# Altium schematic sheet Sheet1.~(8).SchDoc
size A4
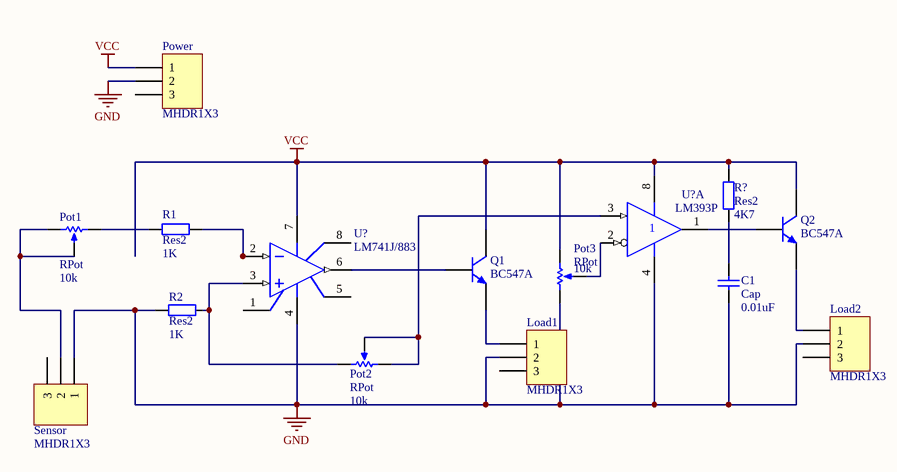
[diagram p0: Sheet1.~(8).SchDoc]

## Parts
(Parts that share a designator on the sheet are numbered #1, #2 ... from top to bottom, then left to right.)
C1  Cap  value 0.01uF  [RAD-0.3]
Load1  MHDR1X3  [MHDR1X3]
Load2  MHDR1X3  [MHDR1X3]
Pot1  RPot  value 10k  [VR5]
Pot2  RPot  value 10k  [VR5]
Pot3  RPot  value 10k  [VR5]
Power  MHDR1X3  [MHDR1X3]
Q1  BC547A  [SOT54]
Q2  BC547A  [SOT54]
R1  Res2  value 1K  [AXIAL-0.4]
R2  Res2  value 1K  [AXIAL-0.4]
R?  Res2  value 4K7  [AXIAL-0.4]
Sensor  MHDR1X3  [MHDR1X3]
U?#1  LM393P  [P008]  (part A of 2)
U?#2  LM741J/883  [N08E]

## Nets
GND: C1.1 Load1.2 Load2.2 Pot3.1(TOP) Power.2 R2.1 Sensor.1 U?#1.4(GND) U?#2.4(V-)
VCC: Pot3.2(BOT) Power.1 Q1.3(C) Q2.3(C) R?.2 U?#1.8(VCC) U?#2.7(V+)
NetC1_2: C1.2 R?.1
NetLoad1_1: Load1.1 Q1.1(E)
NetLoad2_1: Load2.1 Q2.1(E)
NetPot1_1: Pot1.1(TOP) Pot1.3(TAP) Sensor.2
NetPot1_2: Pot1.2(BOT) R1.1
NetPot2_1: Pot2.1(TOP) Pot2.3(TAP) U?#1.3(IN+)
NetPot2_2: Pot2.2(BOT) R2.2 U?#2.3(IN+)
NetPot3_3: Pot3.3(TAP) U?#1.2(IN-)
NetQ1_2: Q1.2(B) U?#2.6(OUT)
NetQ2_2: Q2.2(B) U?#1.1(OUT)
NetR1_2: R1.2 U?#2.2(IN-)

Not connected (* = marked no-connect by the designer): Load1 3; Load2 3; Power 3; Sensor 3; U?#2 1(OS_NULL) 5(OS_NULL) 8(NC)

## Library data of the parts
C1 = Cap: Capacitor
Load1 Load2 Power Sensor = MHDR1X3: Header, 3-Pin
Pot1-Pot3 = RPot: Potentiometer; Sim Note: Enter the Resistance value and the set point into parameter fields.; Set Position: 0.5
Q1 Q2 = BC547A: NPN General-purpose Transistor
R1 R2 R? = Res2: Resistor
U?#1 = LM393P: Dual Differential Comparator
U?#2 = LM741J/883: Operational Amplifier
